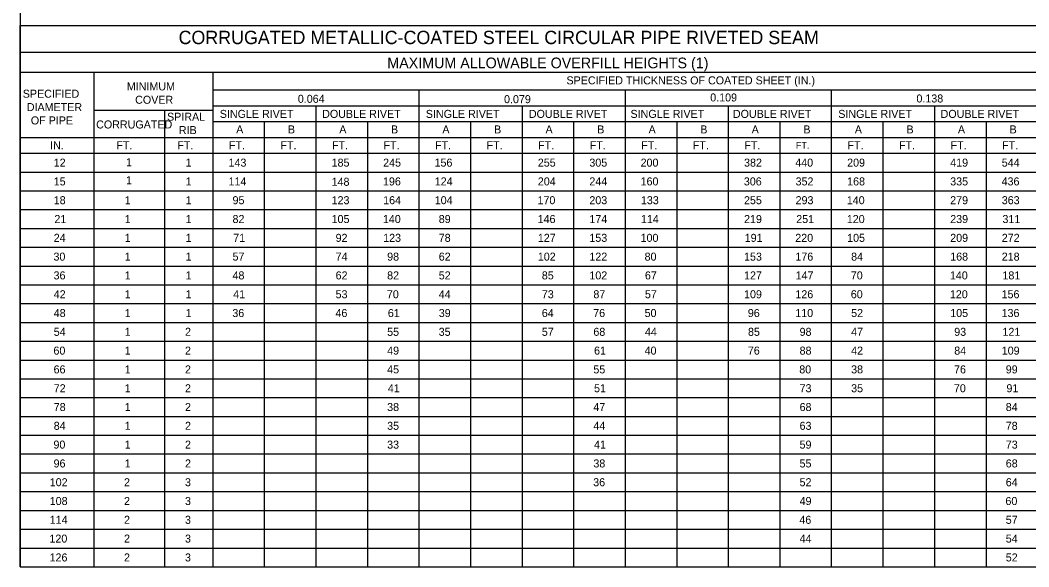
# Model space of a CAD drawing. Extents: x -439.1 to -407.9, y -458.1 to -436.2.
# Drawn here: x -439.11 to -420.2, y -458.05 to -447.81 of the extents above; entities that cross this region are included whole.
import ezdxf

# ---------------------------------------------------------------- set-up
doc = ezdxf.new("R2010")
doc.units = 0
doc.layers.add('Draft_Named_Boundary', color=7, linetype='Continuous')
doc.layers.add('Level 4', color=7, linetype='Continuous')

msp = doc.modelspace()

# ---------------------------------------------------------------- linework, layer by layer
at = {"layer": 'Draft_Named_Boundary'}
msp.add_lwpolyline([(-439.109, -458.051), (-407.859, -458.051), (-407.859, -437.676), (-439.109, -437.676)], close=True, dxfattribs=at)
at = {"layer": 'Level 4'}
for p, q in [((-439.109, -447.908), (-416.17, -447.908)), ((-439.109, -458.051), (-439.109, -447.908)), ((-439.109, -448.409), (-416.17, -448.409)), ((-439.109, -448.785), (-416.17, -448.785)), ((-437.72, -458.051), (-437.72, -448.785)), ((-435.493, -458.051), (-435.493, -448.785)), ((-435.493, -449.113), (-416.17, -449.113)), ((-431.629, -458.051), (-431.629, -449.113)), ((-427.764, -458.051), (-427.764, -449.113)), ((-423.9, -458.051), (-423.9, -449.113)), ((-437.72, -449.495), (-435.493, -449.495)), ((-436.396, -458.051), (-436.396, -449.495)), ((-435.493, -449.411), (-416.17, -449.411)), ((-433.561, -458.051), (-433.561, -449.411)), ((-429.696, -458.051), (-429.696, -449.411)), ((-425.832, -458.051), (-425.832, -449.411)), ((-421.967, -458.051), (-421.967, -449.411)), ((-435.493, -449.708), (-416.17, -449.708)), ((-434.527, -458.051), (-434.527, -449.708)), ((-432.595, -458.051), (-432.595, -449.708)), ((-430.663, -458.051), (-430.663, -449.708)), ((-428.73, -458.051), (-428.73, -449.708)), ((-426.798, -458.051), (-426.798, -449.708)), ((-424.866, -458.051), (-424.866, -449.708)), ((-422.933, -458.051), (-422.933, -449.708)), ((-421.001, -458.051), (-421.001, -449.708)), ((-439.109, -450.005), (-416.17, -450.005)), ((-439.109, -450.302), (-416.17, -450.302)), ((-439.109, -450.654), (-416.17, -450.654)), ((-439.109, -451.006), (-416.17, -451.006)), ((-439.109, -451.359), (-416.17, -451.359)), ((-439.109, -451.711), (-416.17, -451.711)), ((-439.109, -452.063), (-416.17, -452.063)), ((-439.109, -452.415), (-416.17, -452.415)), ((-439.109, -452.767), (-416.17, -452.767)), ((-439.109, -453.12), (-416.17, -453.12)), ((-439.109, -453.472), (-416.17, -453.472)), ((-439.109, -453.824), (-416.17, -453.824)), ((-439.109, -454.176), (-416.17, -454.176)), ((-439.109, -454.529), (-416.17, -454.529)), ((-439.109, -454.881), (-416.17, -454.881)), ((-439.109, -455.233), (-416.17, -455.233)), ((-439.109, -455.585), (-416.17, -455.585)), ((-439.109, -455.937), (-416.17, -455.937)), ((-439.109, -456.29), (-416.17, -456.29)), ((-439.109, -456.642), (-416.17, -456.642)), ((-439.109, -456.994), (-416.17, -456.994)), ((-439.109, -457.346), (-416.17, -457.346)), ((-439.109, -457.699), (-416.17, -457.699)), ((-439.109, -458.051), (-416.17, -458.051))]:
    msp.add_line(p, q, dxfattribs=at)

# ---------------------------------------------------------------- texts
for s, height, p in [('CORRUGATED METALLIC-COATED STEEL CIRCULAR PIPE RIVETED SEAM', 0.25, (-436.14, -448.258)), ('MAXIMUM ALLOWABLE OVERFILL HEIGHTS (1)', 0.2, (-432.228, -448.71)), ('MINIMUM', 0.15, (-437.11, -449.125)), ('SPECIFIED THICKNESS OF COATED SHEET (IN.)', 0.15, (-428.87, -449.012)), ('SPECIFIED', 0.15, (-439.06, -449.262)), ('COVER', 0.15, (-436.954, -449.375)), ('0.064', 0.15, (-433.905, -449.357)), ('0.079', 0.15, (-430.04, -449.364)), ('0.109', 0.15, (-426.176, -449.332)), ('0.138', 0.15, (-422.311, -449.351)), ('DIAMETER', 0.15, (-438.985, -449.512)), ('SPIRAL', 0.15, (-436.356, -449.693)), ('SINGLE RIVET', 0.15, (-435.368, -449.64)), ('DOUBLE RIVET', 0.15, (-433.449, -449.64)), ('SINGLE RIVET', 0.15, (-431.506, -449.64)), ('DOUBLE RIVET', 0.15, (-429.575, -449.64)), ('SINGLE RIVET', 0.15, (-427.67, -449.64)), ('DOUBLE RIVET', 0.15, (-425.751, -449.64)), ('SINGLE RIVET', 0.15, (-423.776, -449.64)), ('DOUBLE RIVET', 0.15, (-421.858, -449.64)), ('OF PIPE', 0.15, (-438.909, -449.762)), ('CORRUGATED', 0.15, (-437.685, -449.838)), ('RIB', 0.15, (-436.135, -449.943)), ('A', 0.15, (-435.06, -449.931)), ('B', 0.15, (-434.091, -449.931)), ('A', 0.15, (-433.128, -449.931)), ('B', 0.15, (-432.159, -449.931)), ('A', 0.15, (-431.196, -449.931)), ('B', 0.15, (-430.227, -449.931)), ('A', 0.15, (-429.263, -449.931)), ('B', 0.15, (-428.294, -449.931)), ('A', 0.15, (-427.331, -449.931)), ('B', 0.15, (-426.362, -449.931)), ('A', 0.15, (-425.399, -449.931)), ('B', 0.15, (-424.43, -449.931)), ('A', 0.15, (-423.466, -449.931)), ('B', 0.15, (-422.498, -449.931)), ('A', 0.15, (-421.534, -449.931)), ('B', 0.15, (-420.565, -449.931)), ('IN.', 0.15, (-438.548, -450.228)), ('FT.', 0.15, (-437.306, -450.228)), ('FT.', 0.15, (-436.164, -450.228)), ('FT.', 0.15, (-435.197, -450.228)), ('FT.', 0.15, (-434.231, -450.228)), ('FT.', 0.15, (-433.265, -450.228)), ('FT.', 0.15, (-432.299, -450.228)), ('FT.', 0.15, (-431.333, -450.228)), ('FT.', 0.15, (-430.367, -450.228)), ('FT.', 0.15, (-429.401, -450.228)), ('FT.', 0.15, (-428.434, -450.228)), ('FT.', 0.15, (-427.468, -450.228)), ('FT.', 0.15, (-426.502, -450.228)), ('FT.', 0.15, (-425.536, -450.228)), ('FT.', 0.1265, (-424.57, -450.217)), ('FT.', 0.15, (-423.604, -450.228)), ('FT.', 0.15, (-422.638, -450.228)), ('FT.', 0.15, (-421.671, -450.228)), ('FT.', 0.15, (-420.705, -450.228)), ('12', 0.15, (-438.48, -450.553)), ('1', 0.15, (-437.125, -450.545)), ('1', 0.15, (-436.008, -450.553)), ('143', 0.15, (-435.204, -450.553)), ('185', 0.15, (-433.272, -450.553)), ('245', 0.15, (-432.306, -450.553)), ('156', 0.15, (-431.343, -450.553)), ('255', 0.15, (-429.407, -450.553)), ('305', 0.15, (-428.441, -450.553)), ('200', 0.15, (-427.481, -450.553)), ('382', 0.15, (-425.542, -450.553)), ('440', 0.15, (-424.582, -450.553)), ('209', 0.15, (-423.61, -450.553)), ('419', 0.15, (-421.678, -450.553)), ('544', 0.15, (-420.712, -450.553)), ('15', 0.15, (-438.48, -450.905)), ('1', 0.15, (-437.125, -450.882)), ('1', 0.15, (-436.008, -450.905)), ('114', 0.15, (-435.204, -450.905)), ('148', 0.15, (-433.272, -450.912)), ('196', 0.15, (-432.309, -450.905)), ('124', 0.15, (-431.339, -450.905)), ('204', 0.15, (-429.407, -450.905)), ('244', 0.15, (-428.441, -450.905)), ('160', 0.15, (-427.481, -450.905)), ('306', 0.15, (-425.546, -450.905)), ('352', 0.15, (-424.576, -450.905)), ('168', 0.15, (-423.61, -450.905)), ('335', 0.15, (-421.678, -450.905)), ('436', 0.15, (-420.715, -450.905)), ('18', 0.15, (-438.48, -451.257)), ('1', 0.15, (-437.15, -451.257)), ('1', 0.15, (-436.008, -451.257)), ('95', 0.15, (-435.129, -451.257)), ('123', 0.15, (-433.272, -451.257)), ('164', 0.15, (-432.306, -451.257)), ('104', 0.15, (-431.339, -451.257)), ('170', 0.15, (-429.413, -451.257)), ('203', 0.15, (-428.441, -451.257)), ('133', 0.15, (-427.475, -451.257)), ('255', 0.15, (-425.543, -451.257)), ('293', 0.15, (-424.576, -451.257)), ('140', 0.15, (-423.616, -451.257)), ('279', 0.15, (-421.678, -451.257)), ('363', 0.15, (-420.712, -451.257)), ('21', 0.15, (-438.467, -451.61)), ('1', 0.15, (-437.15, -451.61)), ('1', 0.15, (-436.008, -451.61)), ('82', 0.15, (-435.129, -451.61)), ('105', 0.15, (-433.272, -451.61)), ('140', 0.15, (-432.311, -451.61)), ('89', 0.15, (-431.264, -451.61)), ('146', 0.15, (-429.411, -451.61)), ('174', 0.15, (-428.441, -451.61)), ('114', 0.15, (-427.475, -451.61)), ('219', 0.15, (-425.542, -451.61)), ('251', 0.15, (-424.564, -451.61)), ('120', 0.15, (-423.616, -451.61)), ('239', 0.15, (-421.678, -451.61)), ('311', 0.15, (-420.699, -451.61)), ('24', 0.15, (-438.48, -451.962)), ('1', 0.15, (-437.15, -451.962)), ('1', 0.15, (-436.008, -451.962)), ('71', 0.15, (-435.116, -451.962)), ('92', 0.15, (-433.197, -451.962)), ('123', 0.15, (-432.306, -451.962)), ('78', 0.15, (-431.264, -451.962)), ('127', 0.15, (-429.407, -451.962)), ('153', 0.15, (-428.441, -451.962)), ('100', 0.15, (-427.481, -451.962)), ('191', 0.15, (-425.53, -451.962)), ('220', 0.15, (-424.582, -451.962)), ('105', 0.15, (-423.61, -451.962)), ('209', 0.15, (-421.678, -451.962)), ('272', 0.15, (-420.712, -451.962)), ('30', 0.15, (-438.485, -452.314)), ('1', 0.15, (-437.15, -452.314)), ('1', 0.15, (-436.008, -452.314)), ('57', 0.15, (-435.129, -452.314)), ('74', 0.15, (-433.197, -452.314)), ('98', 0.15, (-432.231, -452.314)), ('62', 0.15, (-431.264, -452.314)), ('102', 0.15, (-429.407, -452.314)), ('122', 0.15, (-428.441, -452.314)), ('80', 0.15, (-427.406, -452.314)), ('153', 0.15, (-425.542, -452.314)), ('176', 0.15, (-424.58, -452.314)), ('84', 0.15, (-423.535, -452.314)), ('168', 0.15, (-421.678, -452.314)), ('218', 0.15, (-420.712, -452.314)), ('36', 0.15, (-438.483, -452.666)), ('1', 0.15, (-437.15, -452.666)), ('1', 0.15, (-436.008, -452.666)), ('48', 0.15, (-435.129, -452.666)), ('62', 0.15, (-433.197, -452.666)), ('82', 0.15, (-432.231, -452.666)), ('52', 0.15, (-431.264, -452.666)), ('85', 0.15, (-429.332, -452.666)), ('102', 0.15, (-428.441, -452.666)), ('67', 0.15, (-427.4, -452.666)), ('127', 0.15, (-425.542, -452.666)), ('147', 0.15, (-424.576, -452.666)), ('70', 0.15, (-423.541, -452.666)), ('140', 0.15, (-421.684, -452.666)), ('181', 0.15, (-420.699, -452.666)), ('42', 0.15, (-438.48, -453.019)), ('1', 0.15, (-437.15, -453.019)), ('1', 0.15, (-436.008, -453.019)), ('41', 0.15, (-435.116, -453.019)), ('53', 0.15, (-433.197, -453.019)), ('70', 0.15, (-432.236, -453.019)), ('44', 0.15, (-431.264, -453.019)), ('73', 0.15, (-429.332, -453.019)), ('87', 0.15, (-428.366, -453.019)), ('57', 0.15, (-427.4, -453.019)), ('109', 0.15, (-425.542, -453.019)), ('126', 0.15, (-424.58, -453.019)), ('60', 0.15, (-423.541, -453.019)), ('120', 0.15, (-421.684, -453.019)), ('156', 0.15, (-420.715, -453.019)), ('48', 0.15, (-438.48, -453.371)), ('1', 0.15, (-437.15, -453.371)), ('1', 0.15, (-436.008, -453.371)), ('36', 0.15, (-435.133, -453.371)), ('46', 0.15, (-433.2, -453.371)), ('61', 0.15, (-432.218, -453.371)), ('39', 0.15, (-431.264, -453.371)), ('64', 0.15, (-429.332, -453.371)), ('76', 0.15, (-428.369, -453.371)), ('50', 0.15, (-427.406, -453.371)), ('96', 0.15, (-425.471, -453.371)), ('110', 0.15, (-424.582, -453.371)), ('52', 0.15, (-423.535, -453.371)), ('105', 0.15, (-421.678, -453.371)), ('136', 0.15, (-420.715, -453.371)), ('54', 0.15, (-438.48, -453.723)), ('1', 0.15, (-437.15, -453.723)), ('2', 0.15, (-436.02, -453.723)), ('55', 0.15, (-432.231, -453.723)), ('35', 0.15, (-431.265, -453.723)), ('57', 0.15, (-429.332, -453.723)), ('68', 0.15, (-428.366, -453.723)), ('44', 0.15, (-427.4, -453.723)), ('85', 0.15, (-425.468, -453.723)), ('98', 0.15, (-424.501, -453.723)), ('47', 0.15, (-423.535, -453.723)), ('93', 0.15, (-421.603, -453.723)), ('121', 0.15, (-420.699, -453.723)), ('60', 0.15, (-438.485, -454.075)), ('1', 0.15, (-437.15, -454.075)), ('2', 0.15, (-436.02, -454.075)), ('49', 0.15, (-432.231, -454.075)), ('61', 0.15, (-428.353, -454.075)), ('40', 0.15, (-427.406, -454.075)), ('76', 0.15, (-425.471, -454.075)), ('88', 0.15, (-424.501, -454.075)), ('42', 0.15, (-423.535, -454.075)), ('84', 0.15, (-421.603, -454.075)), ('109', 0.15, (-420.712, -454.075)), ('66', 0.15, (-438.483, -454.427)), ('1', 0.15, (-437.15, -454.427)), ('2', 0.15, (-436.02, -454.427)), ('45', 0.15, (-432.231, -454.427)), ('55', 0.15, (-428.366, -454.427)), ('80', 0.15, (-424.507, -454.427)), ('38', 0.15, (-423.535, -454.427)), ('76', 0.15, (-421.606, -454.427)), ('99', 0.15, (-420.637, -454.427)), ('72', 0.15, (-438.48, -454.78)), ('1', 0.15, (-437.15, -454.78)), ('2', 0.15, (-436.02, -454.78)), ('41', 0.15, (-432.218, -454.78)), ('51', 0.15, (-428.353, -454.78)), ('73', 0.15, (-424.501, -454.78)), ('35', 0.15, (-423.535, -454.78)), ('70', 0.15, (-421.609, -454.78)), ('91', 0.15, (-420.624, -454.78)), ('78', 0.15, (-438.48, -455.132)), ('1', 0.15, (-437.15, -455.132)), ('2', 0.15, (-436.02, -455.132)), ('38', 0.15, (-432.231, -455.132)), ('47', 0.15, (-428.366, -455.132)), ('68', 0.15, (-424.501, -455.132)), ('84', 0.15, (-420.637, -455.132)), ('84', 0.15, (-438.48, -455.484)), ('1', 0.15, (-437.15, -455.484)), ('2', 0.15, (-436.02, -455.484)), ('35', 0.15, (-432.231, -455.484)), ('44', 0.15, (-428.366, -455.484)), ('63', 0.15, (-424.501, -455.484)), ('78', 0.15, (-420.637, -455.484)), ('90', 0.15, (-438.485, -455.836)), ('1', 0.15, (-437.15, -455.836)), ('2', 0.15, (-436.02, -455.836)), ('33', 0.15, (-432.231, -455.836)), ('41', 0.15, (-428.353, -455.836)), ('59', 0.15, (-424.501, -455.836)), ('73', 0.15, (-420.637, -455.836)), ('96', 0.15, (-438.483, -456.189)), ('1', 0.15, (-437.15, -456.189)), ('2', 0.15, (-436.02, -456.189)), ('38', 0.15, (-428.366, -456.189)), ('55', 0.15, (-424.502, -456.189)), ('68', 0.15, (-420.637, -456.189)), ('102', 0.15, (-438.555, -456.541)), ('2', 0.15, (-437.163, -456.541)), ('3', 0.15, (-436.02, -456.541)), ('36', 0.15, (-428.369, -456.541)), ('52', 0.15, (-424.501, -456.541)), ('64', 0.15, (-420.637, -456.541)), ('108', 0.15, (-438.555, -456.893)), ('2', 0.15, (-437.163, -456.893)), ('3', 0.15, (-436.02, -456.893)), ('49', 0.15, (-424.501, -456.893)), ('60', 0.15, (-420.643, -456.893)), ('114', 0.15, (-438.555, -457.245)), ('2', 0.15, (-437.163, -457.245)), ('3', 0.15, (-436.02, -457.245)), ('46', 0.15, (-424.505, -457.245)), ('57', 0.15, (-420.637, -457.245)), ('120', 0.15, (-438.56, -457.597)), ('2', 0.15, (-437.163, -457.597)), ('3', 0.15, (-436.02, -457.597)), ('44', 0.15, (-424.501, -457.597)), ('54', 0.15, (-420.637, -457.597)), ('126', 0.15, (-438.558, -457.95)), ('2', 0.15, (-437.163, -457.95)), ('3', 0.15, (-436.02, -457.95)), ('52', 0.15, (-420.637, -457.95))]:
    msp.add_text(s, height=height, dxfattribs=at).set_placement(p)

doc.saveas('drawing.dxf')
